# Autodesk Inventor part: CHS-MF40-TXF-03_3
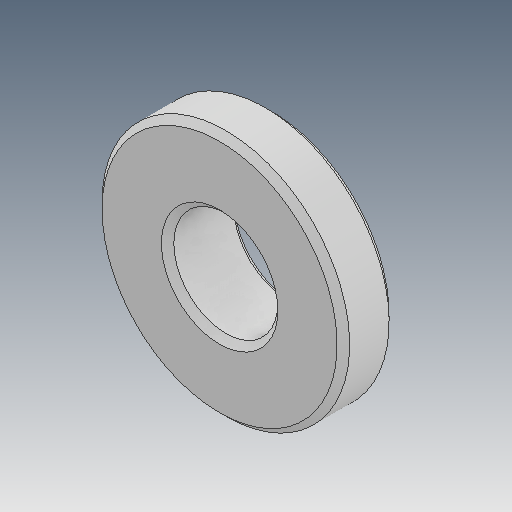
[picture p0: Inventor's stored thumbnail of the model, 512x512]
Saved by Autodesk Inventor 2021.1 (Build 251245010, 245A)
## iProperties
Created: 2019-05
Part Number: CHS-MF40-TXF-03_3
Material: Ogólny
Document SubType Name: Modeling
Designer: user
Density: 1 g/cm^3
Appearance: Domyślna
Author: user
Revision Number: ÈÎºÎ
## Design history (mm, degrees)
feature "ÊäÈë1"
node "Bryła1"
